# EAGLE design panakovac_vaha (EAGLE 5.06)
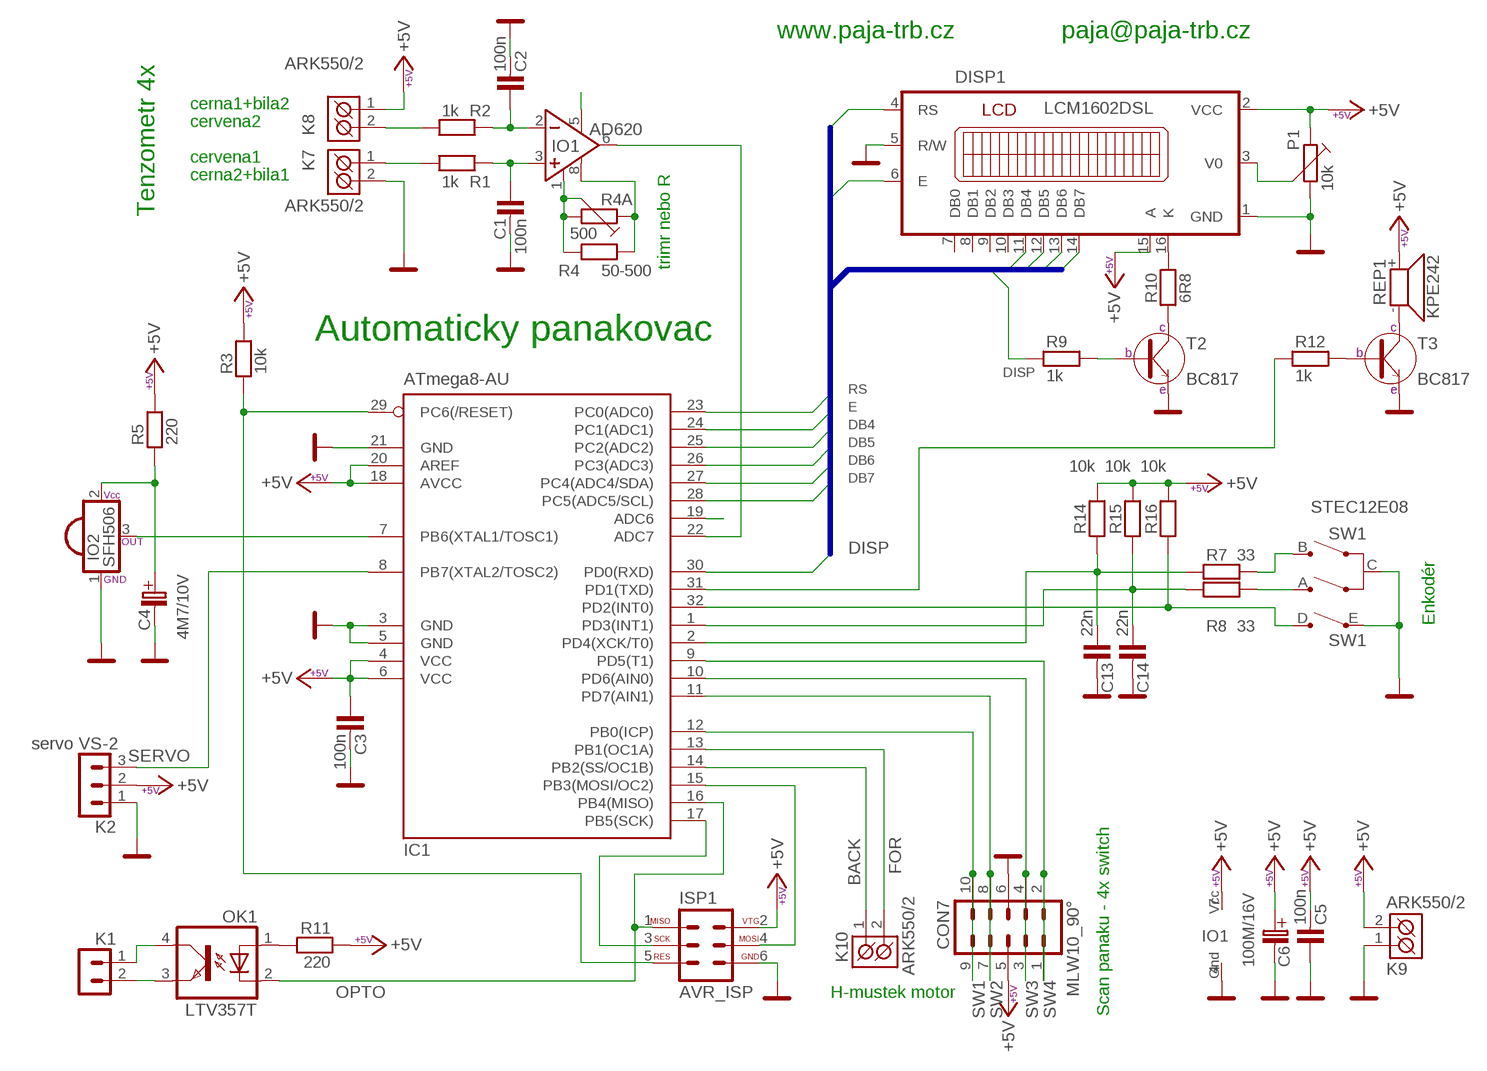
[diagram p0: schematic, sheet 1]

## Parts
C1  100n  C-KERAMIK_SMD_0805  [0805]
C2  100n  C-KERAMIK_SMD_0805  [0805]
C3  100n  C-KERAMIK_SMD_0805  [0805]
C4  4M7/10V  [A]
C5  100n  C-KERAMIK_SMD_1206  [1206]
C6  100M/16V  100M/16V_SMD  [C_EL-SMD_D]
C13  22n  C-KERAMIK_SMD_1206  [1206]
C14  22n  C-KERAMIK_SMD_1206  [1206]
CON7  MLW10_90°  [MLW10A]
DISP1  LCM1602DSL  [LCM1602DSL]
IC1  ATmega8-AU  MEGA8-AI  [TQFP32-08]
IO1  AD620  [DIL8]
IO2  SFH506  [SFH506]
ISP1  AVR_ISP  [MLW06G]
K1  PSH02-02W  [PSH02-02W]
K2  servo VS-2  PSH02-03W  [PSH02-03W]
K7  ARK550/2  [ARK550/2]
K8  ARK550/2  [ARK550/2]
K9  ARK550/2  [ARK550/2]
K10  ARK550/2  [ARK550/2]
OK1  LTV357T  LTV816S  [SMD4]
P1  10k  TRIMRPT6V  [PT6V]
R1  1k  R_SMD_0805  [0805]
R2  1k  R_SMD_0805  [0805]
R3  10k  R_SMD_1206  [1206]
R4  50-500  R_SMD_1206  [1206]
R4A  500  TRIMR64W  [64W]
R5  220  R_SMD_1206  [1206]
R7  33  R_SMD_1206  [1206]
R8  33  R_SMD_1206  [1206]
R9  1k  R_SMD_1206  [1206]
R10  6R8  R_SMD_1206  [1206]
R11  220  R_SMD_1206  [1206]
R12  1k  R_SMD_1206  [1206]
R14  10k  R_SMD_1206  [1206]
R15  10k  R_SMD_1206  [1206]
R16  10k  R_SMD_1206  [1206]
REP1  KPE242  [KPE242]
SW1  STEC12E08  KODER_ROTACNIEC12  [EC12]
T2  BC817  [SOT-23]
T3  BC817  [SOT-23]

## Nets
+5V: C3.1 C5.2 C6.+(C_EL+) CON7.5 DISP1.2(VCC) DISP1.15(A) IC1.4(VCC) IC1.6(VCC) IC1.18(AVCC) IC1.20(AREF) IO1.7(VCC) ISP1.2 K2.2 K8.1(K1) K9.2(K2) P1.1 R3.2 R5.2 R11.1 R14.2 R15.2 R16.2 REP1.+
A: R8.2 SW1.A(A:A)
ADC6: IC1.19(ADC6)
B: R7.2 SW1.B(A:B)
BACK: IC1.14(PB2(SS/OC1B)) K10.1(K1)
D: IC1.32(PD2(INT0)) R16.1 SW1.D(B:D)
DB4: DISP1.11(DB4) IC1.25(PC2(ADC2))
DB5: DISP1.12(DB5) IC1.26(PC3(ADC3))
DB6: DISP1.13(DB6) IC1.27(PC4(ADC4/SDA))
DB7: DISP1.14(DB7) IC1.28(PC5(ADC5/SCL))
DISP: IC1.30(PD0(RXD)) R9.1
E: DISP1.6(E) IC1.24(PC1(ADC1))
FOR: IC1.13(PB1(OC1A)) K10.2(K2)
GND: C1.2 C2.2 C3.2 C4.-(C_EL-) C5.1 C6.-(C_EL-) C13.2 C14.2 CON7.6 DISP1.1(GND) DISP1.5(R/W) IC1.3(GND) IC1.5(GND) IC1.21(GND) IO1.4(GND) IO2.1(GND) ISP1.6 K2.1 K7.2(K2) K9.1(K1) P1.2 SW1.C(A:C) SW1.E(B:E) T2.2(E) T3.2(E)
MOSI: IC1.15(PB3(MOSI/OC2)) ISP1.4
N$1: IO1.1(R1) R4.1 R4A.2 R4A.3
N$2: IO1.8(R2) R4.2 R4A.1
N$3: K7.1(K1) R1.1
N$4: K8.2(K2) R2.1
N$5: C2.1 IO1.2(IN-) R2.2
N$6: C1.1 IO1.3(NEIN+) R1.2
N$7: IC1.22(ADC7) IO1.6(VYSTUP)
N$9: OK1.1(A) R11.2
N$10: K1.2 OK1.3(EMIT)
N$11: K1.1 OK1.4(COL)
N$12: DISP1.16(K) R10.2
N$13: IC1.17(PB5(SCK)) ISP1.3
N$15: IO1.5(OP)
N$16: C4.+(C_EL+) IO2.2(VCC) R5.1
N$20: C13.1 IC1.2(PD4(XCK/T0)) R7.1 R14.1
N$21: C14.1 IC1.1(PD3(INT1)) R8.1 R15.1
N$26: REP1.- T3.3(C)
N$27: R10.1 T2.3(C)
N$32: R12.2 T3.1(B)
N$33: IC1.31(PD1(TXD)) R12.1
N$34: R9.2 T2.1(B)
OPTO: IC1.16(PB4(MISO)) ISP1.1 OK1.2(C)
RESET: IC1.29(PC6(/RESET)) ISP1.5 R3.1
RS: DISP1.4(RS) IC1.23(PC0(ADC0))
SERVO: IC1.8(PB7(XTAL2/TOSC2)) K2.3
SFH: IC1.7(PB6(XTAL1/TOSC1)) IO2.3(OUT)
SW1: CON7.9 CON7.10 IC1.12(PB0(ICP))
SW2: CON7.7 CON7.8 IC1.11(PD7(AIN1))
SW3: CON7.3 CON7.4 IC1.10(PD6(AIN0))
SW4: CON7.1 CON7.2 IC1.9(PD5(T1))
VO: DISP1.3(V0) P1.3
Unconnected: DISP1.7(DB0) DISP1.8(DB1) DISP1.9(DB2) DISP1.10(DB3)

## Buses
SBERNICE_LCD

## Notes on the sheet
- www.paja-trb.cz | paja@paja-trb.cz
- cerna1+bila2
- cervena2
- cervena1
- cerna2+bila1
- Tenzometr 4x
- trimr nebo R
- Automaticky panakovac
- Enkodér
- H-mustek motor
- Scan panaku - 4x switch

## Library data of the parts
C1-C3 C5 = #PaJa_31:C-KERAMIK: Kondenzator - keramicky
C4 = #PaJa_C-tantal_SMD:4M7/10V
C6 = #PaJa_C-el_2:100M/16V
C13 C14 = #PaJa_22:C-KERAMIK: Kondenzator - keramicky
CON7 = #PaJa_konektory:MLW10: Konektory MLW - vidlice - 10x
DISP1 = #PaJa_displeje:LCM1602DSL: LCD - 2x16 + LED (TME - LCM1602DSL)
IC1 = atmel:MEGA8: MICROCONTROLLER 8 Kbytes FLASH, 1 kbytes SRAM, 512 bytes EEPROM, USART, 6-channel 10 bit ADC, 2-channel 8 bit ADC Pin compatible with Atmega48, ATMega88, ATMega168 Source: avr.lbr
IO1 = #PaJa_31:AD620: Pristrojovy zesilovac
IO2 = #PaJa_31:SFH506: Optoprijimac s tvarovacem - 36 kHz nebo 56 kHz
ISP1 = #PaJa_31:AVR_ISP: AVR ISP konektor (dle standardu)
K1 = #PaJa_konektory:PSH02-02: Konektory se zamkem - vidlice - 2pin
K2 = #PaJa_konektory:PSH02-03: Konektory se zamkem - vidlice - 3pin
K7-K10 = #PaJa_konektory:ARK550/2: Svorkovnice - roztec 3,5mm - dvojita
OK1 = optocoupler:LTV816: OPTO COUPLER Source: LITEON, LTV816.pdf
P1 R4A = #PaJa_31:TRIMR: Trimr
R1-R5 R14-R16 = #PaJa_31:R: Rezistor
R7-R12 = #PaJa_22:R: Rezistor
REP1 = #PaJa_31:KPE242: Piezo-sirenka - 70dB - 3V az 16V
SW1 = #PaJa_22:KODER_ROTACNI: Rotacni koder se spinacem v hrideli www.tme.cz
T2 T3 = #PaJa_22:BC817: SMD tranzistor - NPN - ekv. BC337

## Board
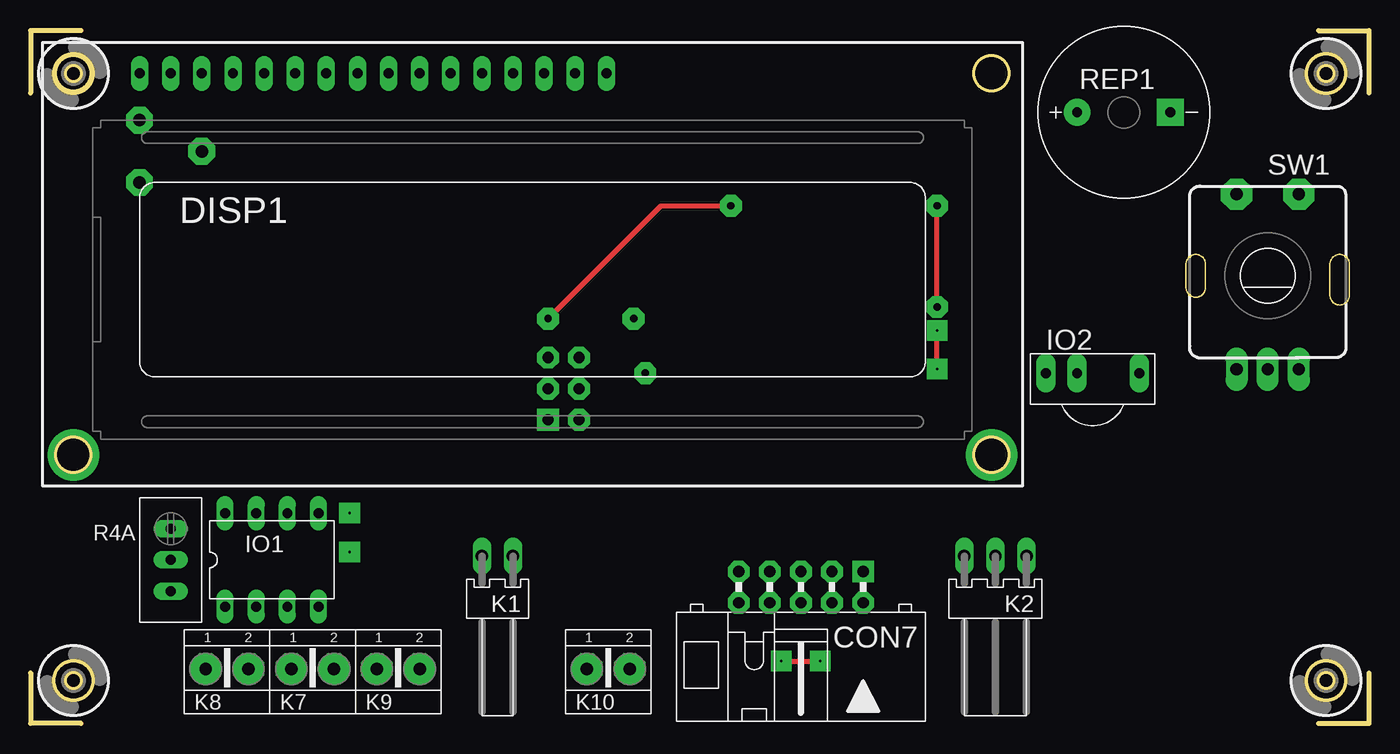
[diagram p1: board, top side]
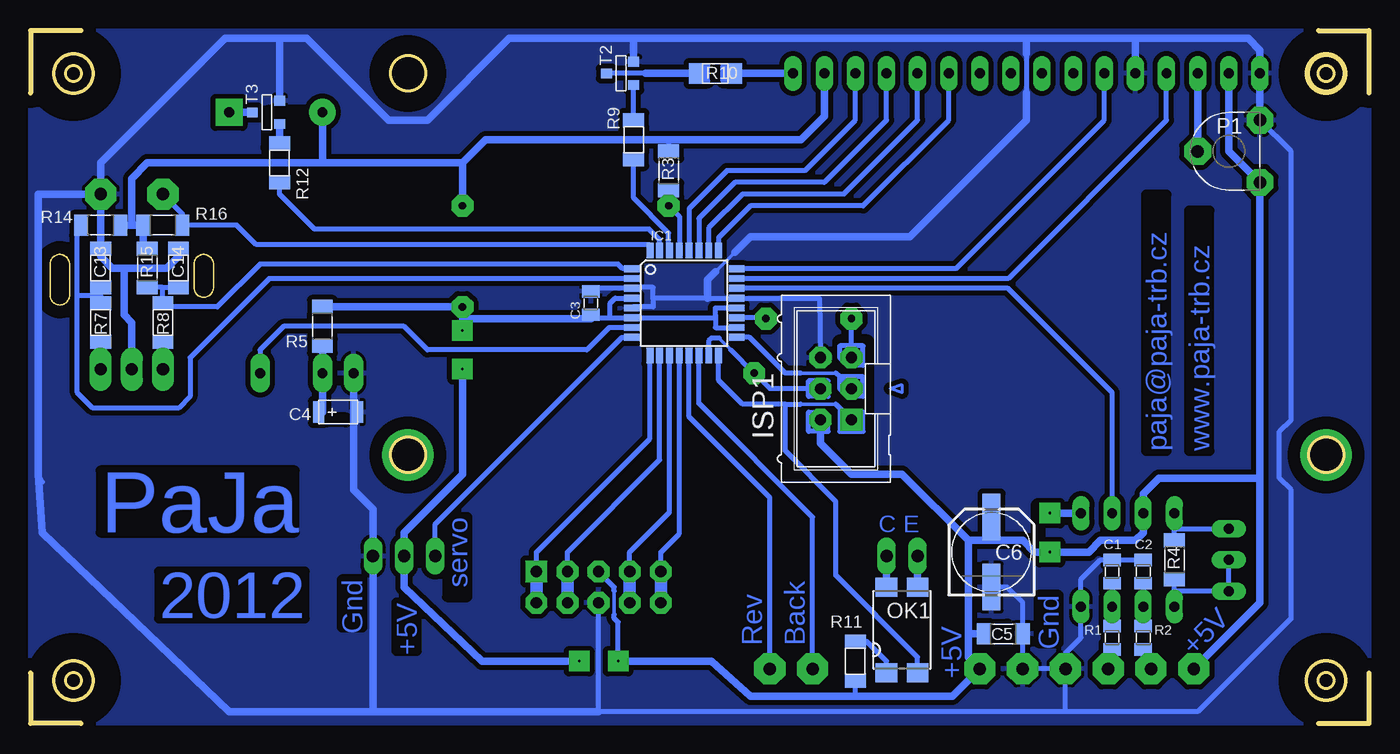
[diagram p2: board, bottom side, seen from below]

Size 109.22 x 56.52 mm. Coordinates in mm from the lower left corner, seen from the top.
Outline: 4.13,56.52 0,56.52 0,51.44
Outline: 109.22,51.44 109.22,56.52 105.09,56.52
Outline: 4.13,0 0,0 0,4.13
Outline: 109.22,4.13 109.22,0 105.09,0
Copper layers (1*16): Top 0.035mm / dielectric 1.5mm / Bottom 0.035mm
Design rules "default": minimum track width 10mil, minimum drill 24mil, track to track 8mil, track to pad 8mil, pad to pad 8mil, via to via 8mil, smd to smd 8mil, copper to edge 40mil, drill to drill 8mil, minimum pad ring 10mil, minimum via ring 8mil, stop-mask expansion 4mil, vias tented up to drill 0mil, thermal gap 10mil
bRestrict: area 97.2,27 to 104.5,41.6; area 12.7,11.1 to 21,14.9; 9 lines

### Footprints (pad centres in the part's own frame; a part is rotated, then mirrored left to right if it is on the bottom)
0805 = smd 1.016 x 1.422: 1 -0.953,0; 2 0.953,0
A = smd 0.914 x 1.778: + 1.587,0; - -1.587,0
1206 = smd 1.143 x 1.702: 1 -1.587,0; 2 1.587,0
C_EL-SMD_D = smd 3.81 x 1.473: + 2.857,0; - -2.857,0
MLW10A = drill 0.914 pad 1.778 square: 1 -5.08,-1.27 | drill 0.914 pad 1.778 octagon: 2 -5.08,1.27; 3 -2.54,-1.27; 4 -2.54,1.27; 5 0,-1.27; 6 0,1.27; 7 2.54,-1.27; 8 2.54,1.27; 9 5.08,-1.27; 10 5.08,1.27
LCM1602DSL = drill 0.813 pad 1.422 long: 1 -32.068,16.828; 2 -29.527,16.828; 3 -26.988,16.828; 4 -24.448,16.828; 5 -21.907,16.828; 6 -19.367,16.828; 7 -16.828,16.828; 8 -14.287,16.828; 9 -11.748,16.828; 10 -9.207,16.828; 11 -6.668,16.828; 12 -4.128,16.828; 13 -1.587,16.828; 14 0.953,16.828; 15 3.493,16.828; 16 6.032,16.828 | hole 2.8: -37.465,-14.287; 37.465,-14.287; 37.465,16.828; -37.465,16.828
TQFP32-08 = smd 1.27 x 0.559: 1 -4.293,2.8; 2 -4.293,2; 3 -4.293,1.2; 4 -4.293,0.4; 5 -4.293,-0.4; 6 -4.293,-1.2; 7 -4.293,-2; 8 -4.293,-2.8; 17 4.293,-2.8; 18 4.293,-2; 19 4.293,-1.2; 20 4.293,-0.4; 21 4.293,0.4; 22 4.293,1.2; 23 4.293,2; 24 4.293,2.8 | smd 0.559 x 1.27: 9 -2.8,-4.293; 10 -2,-4.293; 11 -1.2,-4.293; 12 -0.4,-4.293; 13 0.4,-4.293; 14 1.2,-4.293; 15 2,-4.293; 16 2.8,-4.293; 25 2.8,4.293; 26 2,4.293; 27 1.2,4.293; 28 0.4,4.293; 29 -0.4,4.293; 30 -1.2,4.293; 31 -2,4.293; 32 -2.8,4.293
DIL8 = drill 0.813 pad 1.4 long: 1 -3.81,-3.81; 2 -1.27,-3.81; 3 1.27,-3.81; 4 3.81,-3.81; 5 3.81,3.81; 6 1.27,3.81; 7 -1.27,3.81; 8 -3.81,3.81
SFH506 = drill 0.813 pad 1.6 long: 1 -3.81,0; 2 -1.27,0; 3 3.81,0
MLW06G = drill 0.914 pad 1.778 square: 1 -2.54,-1.27 | drill 0.914 pad 1.778 octagon: 2 -2.54,1.27; 3 0,-1.27; 4 0,1.27; 5 2.54,-1.27; 6 2.54,1.27
PSH02-02W = drill 1.016 pad 1.422 long: 1 -1.27,0; 2 1.27,0
PSH02-03W = drill 1.016 pad 1.422 long: 1 -2.54,0; 2 0,0; 3 2.54,0
ARK550/2 = drill 1.016 pad 2.54 octagon: 1 0,0; 2 3.493,0
SMD4 = smd 1.78 x 1.55: 1 -1.27,-3.5; 2 1.27,-3.5; 3 1.27,3.5; 4 -1.27,3.5
PT6V = drill 1.016 pad 2.184 octagon: 1 -2.54,-2.54; 2 2.54,-2.54; 3 0,2.54
64W = drill 0.813 pad 1.422 long: 1 0,2.54; 2 0,-2.54; 3 0,0
KPE242 = drill 0.813 pad 2.184 round: + -3.81,0 | drill 0.813 pad 2.184 square: - 3.81,0
EC12 = drill 1 pad 1.778 long: A -2.54,-7.62; B 2.54,-7.62; C 0,-7.62 | drill 1 pad 2.54 octagon: D -2.54,6.668; E 2.54,6.668
SOT-23 = smd 0.787 x 0.889: 1 -0.953,-0.953; 2 0.953,-0.953; 3 0,1.27
HOLE_3,0 = hole 3.2: 0,0

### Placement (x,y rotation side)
C1  20.95,12.38 90 bottom
C2  18.41,12.38 90 bottom
C3  63.5,34.29 90 bottom
C4  84.14,25.4 180 bottom
C5  29.84,7.3 180 bottom
C6  30.8,13.97 90 bottom
C13  103.5,37.15 90 bottom
C14  97.16,37.15 90 bottom
CON7  62.87,11.11 180 top
DISP1  40.96,36.2 0 top
IC1  55.88,34.29 0 bottom
IO1  19.69,13.34 0 top
IO2  86.68,28.58 0 top
ISP1  43.5,27.3 90 bottom
K1  38.1,13.65 180 top
K2  78.74,13.65 180 top
K7  21.27,4.45 0 top
K8  14.29,4.45 0 top
K9  28.26,4.45 0 top
K10  45.4,4.45 0 top
OK1  38.1,7.62 0 bottom
P1  11.43,46.67 90 bottom
R1  20.95,6.98 90 bottom
R2  18.41,6.98 90 bottom
R3  57.15,45.09 90 bottom
R4  15.88,13.34 90 bottom
R4A  11.43,13.34 0 top
R5  85.41,32.38 90 bottom
R7  103.5,32.7 270 bottom
R8  98.42,32.7 270 bottom
R9  60.01,47.62 90 bottom
R10  53.34,53.02 0 bottom
R11  41.91,5.08 90 bottom
R12  88.9,45.72 90 bottom
R14  103.5,40.64 0 bottom
R15  99.69,37.15 90 bottom
R16  98.42,40.64 180 bottom
REP1  89.22,49.85 0 top
SW1  100.96,36.51 0 top
T2  60.96,53.02 90 bottom
T3  89.85,49.85 90 bottom
U$1  [HOLE_3,0]  105.73,53.02 0 top
U$2  [HOLE_3,0]  105.73,3.49 0 top
U$3  [HOLE_3,0]  3.49,3.49 0 top
U$4  [HOLE_3,0]  3.49,53.02 0 top

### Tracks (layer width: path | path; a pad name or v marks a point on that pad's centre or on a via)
+5V  (via drill 0.2 pad 1.68, 0.6 pad 1.78)
  Top 0.406: v73.98,33.97 v73.98,42.23 | v61.28,5.08 v64.45,5.08 | v73.98,28.89 v73.98,32.07
  Bottom 0.305: 61.59,8.89 61.59,10.8
  Bottom 0.406: 100.01,38.73 R15.2 | IC1.20 53.34,33.89 53.34,33.34 | IC1.18 53.34,32.29 53.34,33.34 | 53.34,33.34 53.34,33.09 IC1.6 61.91,33.09 | IC1.4 61.51,34.69 61.91,34.29 61.91,33.09 | 61.91,33.09 63.5,33.09 C3.1 63.5,33.02 | 57.15,47.62 R3.2 | 30.8,14.92 C6.+ | 41.91,2.22 R11.1 | CON7.5 61.59,11.11 61.59,10.8 | 61.59,8.89 61.59,8.57 61.28,8.25 v61.28,5.08 | 44.13,23.81 44.13,25.08 44.45,25.4 45.72,25.4 45.72,23.81 44.77,23.81 44.13,23.81
  Bottom 0.61: 100.96,40.64 R14.2 | 100.01,38.73 R16.2 100.96,40.64 | 8.89,20 17.14,20 18.41,18.73 IO1.7 18.41,15.56 19.05,14.92 21.91,14.92 22.86,13.97 v26.03,13.97 27.3,13.97 28.26,14.92 30.8,14.92 32.7,14.92 | 8.89,20 8.89,9.84 K8.1 | 100.96,40.64 100.96,44.45 99.69,45.72 85.41,45.72 | DISP1.2 11.43,46.67 P1.1 8.89,20 | 32.7,7.3 32.7,5.4 K9.2 33.97,2.22 41.91,2.22 50.48,2.22 53.66,5.08 v61.28,5.08 | DISP1.15 44.45,49.53 46.36,47.62 57.15,47.62 72.07,47.62 73.98,45.72 | 32.7,14.92 32.7,7.3 | 32.7,7.3 C5.2 | R5.2 v73.98,33.97 73.98,33.34 | v73.98,42.23 73.98,45.72 | v64.45,5.08 72.39,5.08 78.74,11.11 K2.2 78.74,15.56 73.98,20.32 v73.98,28.89 | v73.98,32.07 73.98,33.34 | ISP1.2 44.77,23.81 44.77,22.86 42.23,20.32 38.1,20.32 32.7,14.92 | 63.5,33.02 73.98,33.02 73.98,33.34 | 85.41,45.72 REP1.+ | 73.98,45.72 85.41,45.72
A
  Bottom 0.406: SW1.A R8.2
ADC6  (via drill 0.6 pad 1.78)
  Bottom 0.406: IC1.19 49.28,33.09 v49.21,33.02
B
  Bottom 0.406: SW1.B R7.2
BACK
  Bottom 0.406: IC1.14 54.68,26.11 45.4,16.83 K10.1
D
  Bottom 0.406: SW1.D 96.84,41.59 R16.1 92.39,40.64 90.8,39.05 58.74,39.05 IC1.32
DB4
  Bottom 0.406: IC1.25 53.08,39.63 50.48,42.23 41.27,42.23 34.29,49.21 DISP1.11
DB5
  Bottom 0.406: IC1.26 53.88,40.42 51.12,43.18 42.86,43.18 36.83,49.21 DISP1.12
DB6
  Bottom 0.406: IC1.27 54.68,41.2 51.75,44.13 44.45,44.13 39.37,49.21 DISP1.13
DB7
  Bottom 0.406: IC1.28 55.48,41.99 52.39,45.09 46.04,45.09 41.91,49.21 DISP1.14
DISP
  Bottom 0.406: 57.15,38.73 57.15,40.01 60.01,42.86 R9.1 | 57.15,38.73 57.15,38.42 | 57.15,38.73 57.08,38.66 IC1.30
E
  Bottom 0.406: IC1.24 33.71,37.09 21.59,49.21 DISP1.6
FOR
  Bottom 0.406: IC1.13 55.48,25 48.9,18.41 K10.2
GND
  Bottom 0.305: 51.75,38.42 53.34,36.83
  Bottom 0.406: C2.2 C1.2 21.91,13.34 23.49,11.75 IO1.4 23.49,6.98 24.77,5.71 K7.2 | IC1.5 60.09,33.97 58.42,33.97 58.42,34.61 | 58.42,34.61 58.42,35.56 60.1,35.56 IC1.3 63.5,35.49 C3.2 | 58.42,34.61 58.42,34.69 53.98,34.69 IC1.21 44.85,34.69 ISP1.6 | K7.2 K9.1 C5.1 28.26,9.84 29.53,11.11 C6.- | 108.58,20.32 108.27,19.69 | 24.77,0.95 K7.2 | 24.77,0.95 62.87,0.95 CON7.6 | 24.77,0.95 13.97,0.95 6.35,8.57 6.35,19.05 7.3,20 7.3,23.81 6.35,24.77 6.35,46.67 P1.2 | 82.87,25.72 C4.- | 27.94,54.61 27.94,51.44
  Bottom 0.61: SW1.C 100.96,32.7 101.6,33.34 101.6,37.15 | 101.6,37.15 98.11,37.15 97.16,38.1 C14.2 | 101.6,37.15 102.55,37.15 103.5,38.1 C13.2 SW1.E | 19.05,55.88 9.84,55.88 8.89,54.93 DISP1.1 P1.2 | 19.05,55.88 DISP1.5 | 19.05,55.88 27.94,55.88 | 27.94,55.88 60.01,55.88 | 60.01,55.88 70.17,55.88 76.83,49.21 80.01,49.21 86.68,55.88 88.9,55.88 | 88.9,55.88 93.34,55.88 103.5,45.72 SW1.E | 88.9,55.88 T3.2 | IO2.1 82.87,25.72 82.87,19.05 81.28,17.46 K2.1 81.28,0.95 | SW1.E 108.58,43.18 108.58,20.32 108.27,15.56 93.03,0.95 81.28,0.95 | 62.87,0.95 81.28,0.95 | 53.34,36.83 53.98,36.19 53.98,34.69 | 51.75,38.42 50.48,39.69 37.46,39.69 27.94,49.21 27.94,51.44 | 27.94,55.88 27.94,54.61 | 60.01,55.88 T2.2
  pour Bottom (isolate 0.406): 0,56.52 0,0 109.22,0 109.22,56.52
MOSI  (via drill 0.6 pad 1.78)
  Bottom 0.305: 52.07,30.48 53.02,31.43
  Bottom 0.406: 45.72,27.3 ISP1.4 | 45.72,27.3 48.9,27.3 v50.16,28.58 52.07,30.48 | IC1.15 53.88,31.21 53.66,31.43 53.02,31.43 | 45.72,27.3 45.72,27.94 44.13,27.94 44.13,26.67 45.72,26.67 45.72,27.3
N$1
  Bottom 0.406: 15.88,10.8 IO1.1 | 15.88,10.8 R4.1 15.56,12.07 | R4A.3 R4A.2 15.88,10.8
N$2
  Bottom 0.406: R4.2 15.88,15.87 | 15.88,15.87 IO1.8 | 15.88,15.87 R4A.1
N$3
  Bottom 0.406: K7.1 20.95,4.76 R1.1
N$4
  Bottom 0.406: K8.2 18.41,5.08 R2.1
N$5
  Bottom 0.406: R2.2 IO1.2 C2.1
N$6
  Bottom 0.406: R1.2 IO1.3 C1.1
N$7
  Bottom 0.406: IC1.22 29.46,35.49 20.95,26.99 IO1.6
N$8  (via drill 1.2 pad 4.2)
  other vias: 3.49,21.91
N$9
  Bottom 0.406: R11.2 40.96,6.67 39.37,5.08 OK1.1
N$10
  Bottom 0.61: OK1.3 K1.2
N$11
  Bottom 0.61: OK1.4 K1.1
N$12
  Bottom 0.61: DISP1.16 49.85,53.02 R10.2
N$13
  Bottom 0.305: 43.5,28.58 46.36,28.58
  Bottom 0.406: 43.18,28.26 ISP1.3 | 43.18,28.26 43.5,28.58 | IC1.17 50.54,31.49 47.62,28.58 46.36,28.58 | 43.18,28.26 41.27,28.26 41.27,26.67 42.55,26.67 43.18,27.3 43.18,28.26
N$14  (via drill 1.2 pad 4.2)
  other vias: 78.42,21.91
N$15  (via drill 0.2 pad 1.68)
  Bottom 0.61: IO1.5 v26.03,17.15
N$16
  Bottom 0.406: C4.+ 85.41,25.4
  Bottom 0.61: 85.41,25.4 IO2.2 R5.1
N$17
  Bottom 0.254: 38.1,27.62 38.1,26.99 39.05,27.3 38.1,27.62
N$18
  Bottom 0.406: 52.39,53.66 52.07,53.66 | 52.39,53.66 52.7,53.66 52.7,52.39 52.39,52.39 | 52.39,52.39 52.07,52.39 | 52.39,52.39 52.39,53.66
N$19
  Bottom 0.406: 54.29,53.66 54.61,53.66 | 54.29,53.66 53.98,53.66 53.98,52.39 54.29,52.39 | 54.29,52.39 54.61,52.39 | 54.29,52.39 54.29,53.66
N$20
  Bottom 0.406: R14.1 105.41,40.64 105.41,34.92 | 105.41,34.92 103.5,34.92 | 103.5,34.92 R7.1 | 103.5,34.92 C13.1 | 105.41,34.92 105.41,26.99 104.14,25.72 97.16,25.72 96.2,26.67 96.2,29.84 89.76,36.29 IC1.2
N$21
  Bottom 0.406: 98.42,35.56 C14.1 | 98.42,35.56 R15.1 | 98.42,35.56 R8.1 98.42,33.97 93.98,33.97 90.49,37.47 61.28,37.47 60.9,37.09 IC1.1
N$26
  Bottom 0.61: T3.3 REP1.-
N$27
  Bottom 0.406: 59.05,53.02 T2.3
  Bottom 0.61: R10.1 59.05,53.02
N$32
  Bottom 0.61: R12.2 T3.1
N$33
  Bottom 0.406: IC1.31 57.88,39.47 58.74,40.32 86.04,40.32 88.9,43.18 R12.1
N$34
  Bottom 0.406: R9.2 T2.1
OPTO
  Bottom 0.305: 46.36,26.04 43.5,26.04
  Bottom 0.406: 43.5,26.04 43.18,25.72 | 43.18,25.72 ISP1.1 | IC1.16 53.08,28 51.12,26.04 47.62,26.04 | 47.62,26.04 46.36,26.04 | 47.62,26.04 47.62,22.23 43.5,18.1 43.5,12.07 36.83,5.4 OK1.2 | 43.18,25.72 42.86,25.4 41.27,25.4 41.27,23.81 43.18,23.81 43.18,25.72
RESET  (via drill 0.6 pad 1.78)
  Top 0.406: v57.15,42.23 51.44,42.23 v42.23,33.02
  Bottom 0.406: R3.1 v57.15,42.23 56.28,41.36 IC1.29 | 42.23,30.8 v42.23,33.02 | 42.23,30.8 41.27,30.8 41.27,29.21 42.55,29.21 43.18,29.84 43.18,30.8 42.23,30.8 | 42.23,30.8 ISP1.5
RS
  Bottom 0.406: IC1.23 29.43,36.29 16.51,49.21 DISP1.4
SERVO
  Bottom 0.406: IC1.8 60.96,31.49 76.2,16.25 K2.3
SFH
  Bottom 0.406: IO2.3 90.49,30.48 88.58,32.38 78.74,32.38 76.83,30.48 63.82,30.48 62.01,32.29 IC1.7
SW1
  Bottom 0.406: IC1.12 56.28,15.48 57.79,13.97 CON7.9
  Bottom 1.016: CON7.10 CON7.9
SW2
  Bottom 0.406: IC1.11 57.08,17.22 60.33,13.97 CON7.7
  Bottom 1.016: CON7.8 CON7.7
SW3
  Bottom 0.406: IC1.10 57.88,21.49 65.41,13.97 CON7.3
  Bottom 1.016: CON7.4 CON7.3
SW4
  Bottom 0.406: IC1.9 58.68,23.23 67.94,13.97 CON7.1
  Bottom 1.016: CON7.2 CON7.1
VO
  Bottom 0.61: P1.3 DISP1.3

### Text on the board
Bottom: www.paja-trb.cz | paja@paja-trb.cz | servo | C E | PaJa | Gnd | Gnd | +5V | +5V | 2012 | Back | Rev | +5V
PaJa: www.paja-trb.unas.cz
Doplnky: SFH
Popisy: cerna | cervena | oranz/zluta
